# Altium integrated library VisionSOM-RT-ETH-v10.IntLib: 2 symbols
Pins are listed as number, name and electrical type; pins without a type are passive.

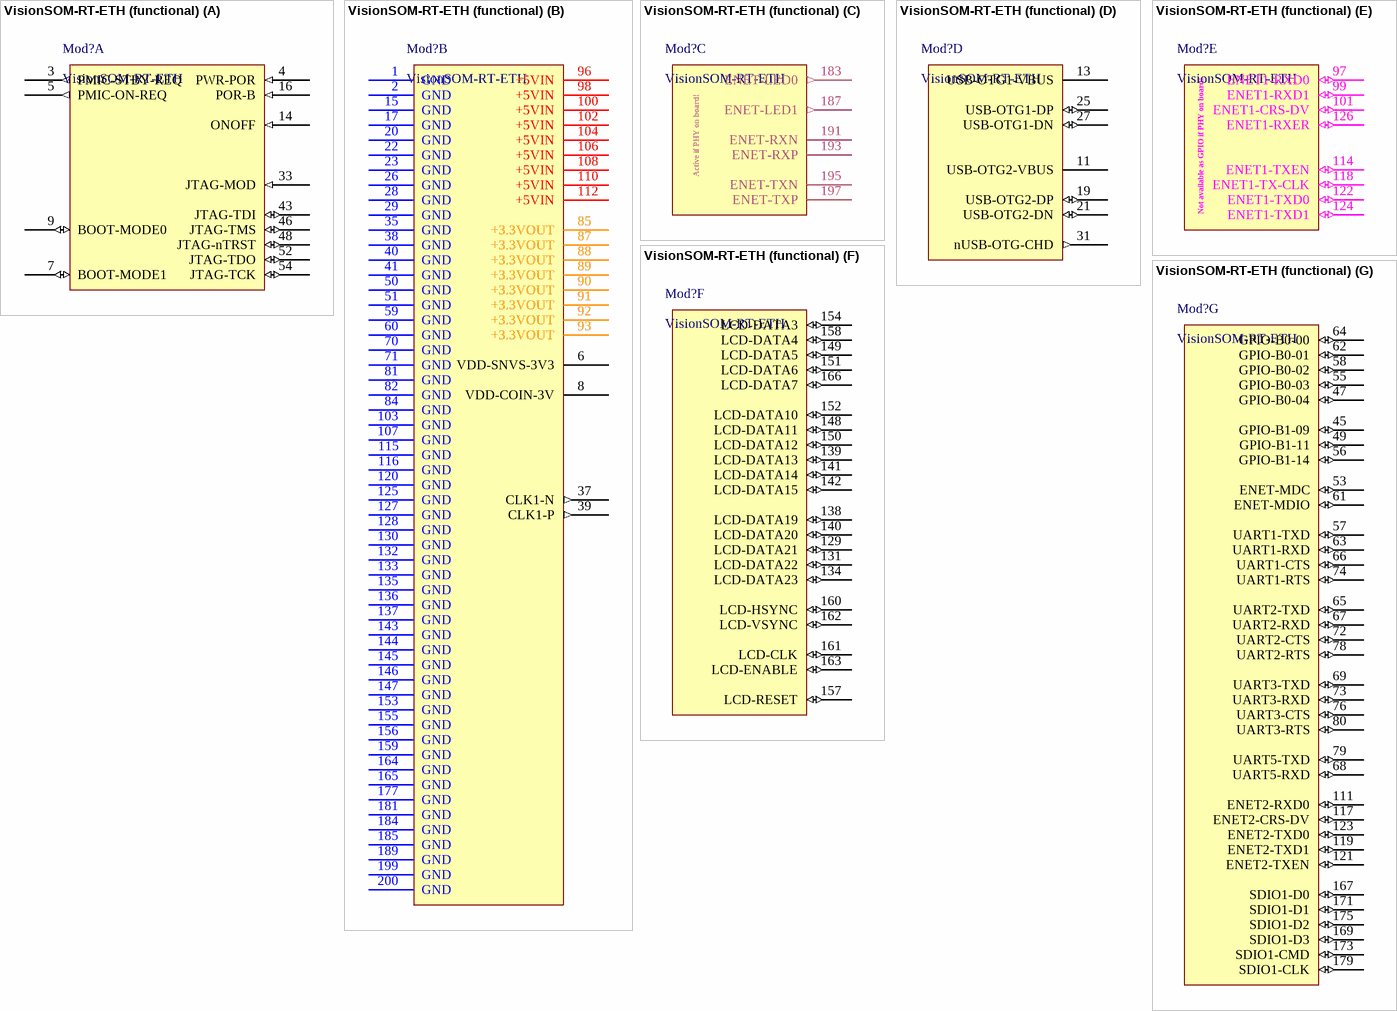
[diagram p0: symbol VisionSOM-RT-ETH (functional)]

## VisionSOM-RT-ETH (functional)
designator Mod?, comment VisionSOM-RT-ETH
Functional SoM view
footprint VisionSOM-RT-ETH (SoMLabs VisionSOM-RT-ETH)
part A pins: 3 PMIC-STBY-REQ (out), 4 PWR-POR (in), 5 PMIC-ON-REQ (out), 7 BOOT-MODE1 (io), 9 BOOT-MODE0 (io), 14 ONOFF (in), 16 POR-B (in), 33 JTAG-MOD (in), 43 JTAG-TDI (io), 46 JTAG-TMS (io), 48 JTAG-nTRST (io), 52 JTAG-TDO (io), 54 JTAG-TCK (io)
part B pins: 1 GND (power), 2 GND (power), 6 VDD-SNVS-3V3 (power), 8 VDD-COIN-3V (power), 15 GND (power), 17 GND (power), 20 GND (power), 22 GND (power), 23 GND (power), 26 GND (power), 28 GND (power), 29 GND (power), 35 GND (power), 37 CLK1-N (out), 38 GND (power), 39 CLK1-P (out), 40 GND (power), 41 GND (power), 50 GND (power), 51 GND (power), 59 GND (power), 60 GND (power), 70 GND (power), 71 GND (power), 81 GND (power), 82 GND (power), 84 GND (power), 85 +3.3VOUT (power), 87 +3.3VOUT (power), 88 +3.3VOUT (power), 89 +3.3VOUT (power), 90 +3.3VOUT (power), 91 +3.3VOUT (power), 92 +3.3VOUT (power), 93 +3.3VOUT (power), 96 +5VIN (power), 98 +5VIN (power), 100 +5VIN (power), 102 +5VIN (power), 103 GND (power), 104 +5VIN (power), 106 +5VIN (power), 107 GND (power), 108 +5VIN (power), 110 +5VIN (power), 112 +5VIN (power), 115 GND (power), 116 GND (power), 120 GND (power), 125 GND (power), 127 GND (power), 128 GND (power), 130 GND (power), 132 GND (power), 133 GND (power), 135 GND (power), 136 GND (power), 137 GND (power), 143 GND (power), 144 GND (power), 145 GND (power), 146 GND (power), 147 GND (power), 153 GND (power), 155 GND (power), 156 GND (power), 159 GND (power), 164 GND (power), 165 GND (power), 177 GND (power), 181 GND (power), 184 GND (power), 185 GND (power), 189 GND (power), 199 GND (power), 200 GND (power)
part C pins: 183 ENET-LED0 (out), 187 ENET-LED1 (out), 191 ENET-RXN, 193 ENET-RXP, 195 ENET-TXN, 197 ENET-TXP
part D pins: 11 USB-OTG2-VBUS (power), 13 USB-OTG1-VBUS (power), 19 USB-OTG2-DP (io), 21 USB-OTG2-DN (io), 25 USB-OTG1-DP (io), 27 USB-OTG1-DN (io), 31 nUSB-OTG-CHD (out)
part E pins: 97 ENET1-RXD0 (io), 99 ENET1-RXD1 (io), 101 ENET1-CRS-DV (io), 114 ENET1-TXEN (io), 118 ENET1-TX-CLK (io), 122 ENET1-TXD0 (io), 124 ENET1-TXD1 (io), 126 ENET1-RXER (io)
part F pins: 129 LCD-DATA21 (io), 131 LCD-DATA22 (io), 134 LCD-DATA23 (io), 138 LCD-DATA19 (io), 139 LCD-DATA13 (io), 140 LCD-DATA20 (io), 141 LCD-DATA14 (io), 142 LCD-DATA15 (io), 148 LCD-DATA11 (io), 149 LCD-DATA5 (io), 150 LCD-DATA12 (io), 151 LCD-DATA6 (io), 152 LCD-DATA10 (io), 154 LCD-DATA3 (io), 157 LCD-RESET (io), 158 LCD-DATA4 (io), 160 LCD-HSYNC (io), 161 LCD-CLK (io), 162 LCD-VSYNC (io), 163 LCD-ENABLE (io), 166 LCD-DATA7 (io)
part G pins: 45 GPIO-B1-09 (io), 47 GPIO-B0-04 (io), 49 GPIO-B1-11 (io), 53 ENET-MDC (io), 55 GPIO-B0-03 (io), 56 GPIO-B1-14 (io), 57 UART1-TXD (io), 58 GPIO-B0-02 (io), 61 ENET-MDIO (io), 62 GPIO-B0-01 (io), 63 UART1-RXD (io), 64 GPIO-B0-00 (io), 65 UART2-TXD (io), 66 UART1-CTS (io), 67 UART2-RXD (io), 68 UART5-RXD (io), 69 UART3-TXD (io), 72 UART2-CTS (io), 73 UART3-RXD (io), 74 UART1-RTS (io), 76 UART3-CTS (io), 78 UART2-RTS (io), 79 UART5-TXD (io), 80 UART3-RTS (io), 111 ENET2-RXD0 (io), 117 ENET2-CRS-DV (io), 119 ENET2-TXD1 (io), 121 ENET2-TXEN (io), 123 ENET2-TXD0 (io), 167 SDIO1-D0 (io), 169 SDIO1-D3 (io), 171 SDIO1-D1 (io), 173 SDIO1-CMD (io), 175 SDIO1-D2 (io), 179 SDIO1-CLK (io)

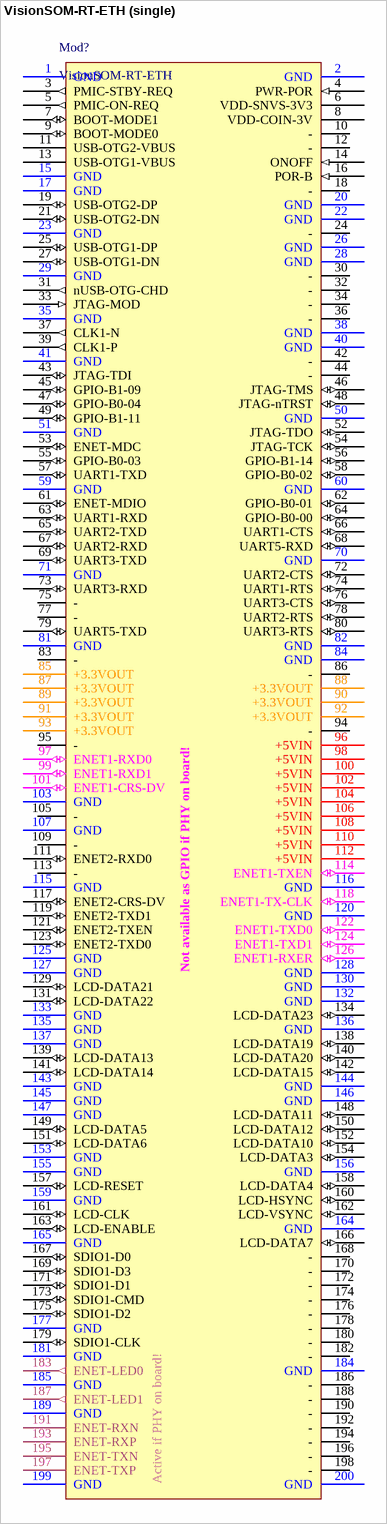
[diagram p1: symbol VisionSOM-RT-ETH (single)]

## VisionSOM-RT-ETH (single)
designator Mod?, comment VisionSOM-RT-ETH
SoM module view
footprint VisionSOM-RT-ETH (SoMLabs VisionSOM-RT-ETH)
pins: 1 GND (power), 2 GND (power), 3 PMIC-STBY-REQ (out), 4 PWR-POR (in), 5 PMIC-ON-REQ (out), 6 VDD-SNVS-3V3 (power), 7 BOOT-MODE1 (io), 8 VDD-COIN-3V (power), 9 BOOT-MODE0 (io), 10 -, 11 USB-OTG2-VBUS (power), 12 -, 13 USB-OTG1-VBUS (power), 14 ONOFF (in), 15 GND (power), 16 POR-B (in), 17 GND (power), 18 -, 19 USB-OTG2-DP (io), 20 GND (power), 21 USB-OTG2-DN (io), 22 GND (power), 23 GND (power), 24 -, 25 USB-OTG1-DP (io), 26 GND (power), 27 USB-OTG1-DN (io), 28 GND (power), 29 GND (power), 30 -, 31 nUSB-OTG-CHD (out), 32 -, 33 JTAG-MOD (in), 34 -, 35 GND (power), 36 -, 37 CLK1-N (out), 38 GND (power), 39 CLK1-P (out), 40 GND (power), 41 GND (power), 42 -, 43 JTAG-TDI (io), 44 -, 45 GPIO-B1-09 (io), 46 JTAG-TMS (io), 47 GPIO-B0-04 (io), 48 JTAG-nTRST (io), 49 GPIO-B1-11 (io), 50 GND (power), 51 GND (power), 52 JTAG-TDO (io), 53 ENET-MDC (io), 54 JTAG-TCK (io), 55 GPIO-B0-03 (io), 56 GPIO-B1-14 (io), 57 UART1-TXD (io), 58 GPIO-B0-02 (io), 59 GND (power), 60 GND (power), 61 ENET-MDIO (io), 62 GPIO-B0-01 (io), 63 UART1-RXD (io), 64 GPIO-B0-00 (io), 65 UART2-TXD (io), 66 UART1-CTS (io), 67 UART2-RXD (io), 68 UART5-RXD (io), 69 UART3-TXD (io), 70 GND (power), 71 GND (power), 72 UART2-CTS (io), 73 UART3-RXD (io), 74 UART1-RTS (io), 75 -, 76 UART3-CTS (io), 77 -, 78 UART2-RTS (io), 79 UART5-TXD (io), 80 UART3-RTS (io), 81 GND (power), 82 GND (power), 83 -, 84 GND (power), 85 +3.3VOUT (power), 86 -, 87 +3.3VOUT (power), 88 +3.3VOUT (power), 89 +3.3VOUT (power), 90 +3.3VOUT (power), 91 +3.3VOUT (power), 92 +3.3VOUT (power), 93 +3.3VOUT (power), 94 -, 95 -, 96 +5VIN (power), 97 ENET1-RXD0 (io), 98 +5VIN (power), 99 ENET1-RXD1 (io), 100 +5VIN (power), 101 ENET1-CRS-DV (io), 102 +5VIN (power), 103 GND (power), 104 +5VIN (power), 105 -, 106 +5VIN (power), 107 GND (power), 108 +5VIN (power), 109 -, 110 +5VIN (power), 111 ENET2-RXD0 (io), 112 +5VIN (power), 113 -, 114 ENET1-TXEN (io), 115 GND (power), 116 GND (power), 117 ENET2-CRS-DV (io), 118 ENET1-TX-CLK (io), 119 ENET2-TXD1 (io), 120 GND (power), 121 ENET2-TXEN (io), 122 ENET1-TXD0 (io), 123 ENET2-TXD0 (io), 124 ENET1-TXD1 (io), 125 GND (power), 126 ENET1-RXER (io), 127 GND (power), 128 GND (power), 129 LCD-DATA21 (io), 130 GND (power), 131 LCD-DATA22 (io), 132 GND (power), 133 GND (power), 134 LCD-DATA23 (io), 135 GND (power), 136 GND (power), 137 GND (power), 138 LCD-DATA19 (io), 139 LCD-DATA13 (io), 140 LCD-DATA20 (io), 141 LCD-DATA14 (io), 142 LCD-DATA15 (io), 143 GND (power), 144 GND (power), 145 GND (power), 146 GND (power), 147 GND (power), 148 LCD-DATA11 (io), 149 LCD-DATA5 (io), 150 LCD-DATA12 (io), 151 LCD-DATA6 (io), 152 LCD-DATA10 (io), 153 GND (power), 154 LCD-DATA3 (io), 155 GND (power), 156 GND (power), 157 LCD-RESET (io), 158 LCD-DATA4 (io), 159 GND (power), 160 LCD-HSYNC (io), 161 LCD-CLK (io), 162 LCD-VSYNC (io), 163 LCD-ENABLE (io), 164 GND (power), 165 GND (power), 166 LCD-DATA7 (io), 167 SDIO1-D0 (io), 168 -, 169 SDIO1-D3 (io), 170 -, 171 SDIO1-D1 (io), 172 -, 173 SDIO1-CMD (io), 174 -, 175 SDIO1-D2 (io), 176 -, 177 GND (power), 178 -, 179 SDIO1-CLK (io), 180 -, 181 GND (power), 182 -, 183 ENET-LED0 (out), 184 GND (power), 185 GND (power), 186 -, 187 ENET-LED1 (out), 188 -, 189 GND (power), 190 -, 191 ENET-RXN, 192 -, 193 ENET-RXP, 194 -, 195 ENET-TXN, 196 -, 197 ENET-TXP, 198 -, 199 GND (power), 200 GND (power)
